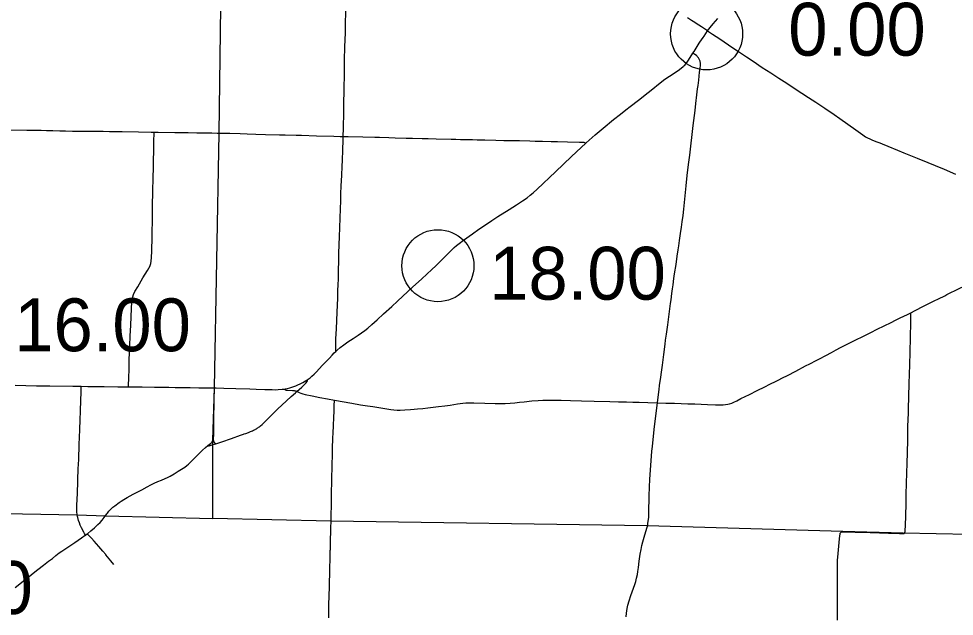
# Model space of a CAD drawing. Extents: x 1813937 to 1948437, y 826606 to 1022856.
# Drawn here: x 1890191 to 1909677, y 927491 to 939932 of the extents above; entities that cross this region are included whole.
import ezdxf

# ---------------------------------------------------------------- set-up
doc = ezdxf.new("R2010")
doc.units = 0
for name, color, linetype in [('Default', 7, 'Continuous'), ('GM_X_County_Road', 7, 'Continuous'), ('GM_X_State_Route', 7, 'Continuous'), ('GM_X_Township', 7, 'Continuous'), ('GM_X_Township_Road', 7, 'Continuous'), ('GM_X_US_Route', 7, 'Continuous')]:
    doc.layers.add(name, color=color, linetype=linetype)

msp = doc.modelspace()

# ---------------------------------------------------------------- linework, layer by layer
at = {"layer": 'Default'}
for centre in [(1904519, 939617), (1898922, 934790)]:
    msp.add_circle(centre, 750, dxfattribs=at)
at = {"layer": 'GM_X_County_Road'}
for points in [[(1904539, 939679), (1904643, 939612), (1904793, 939513), (1905065, 939329), (1905201, 939237), (1905351, 939138), (1905487, 939046), (1905678, 938919), (1905857, 938803), (1906022, 938695), (1906188, 938590), (1906366, 938473), (1906641, 938294), (1906791, 938194), (1906983, 938068), (1907172, 937938), (1907294, 937854), (1907629, 937617), (1907775, 937512), (1907830, 937476), (1907872, 937452), (1907916, 937430), (1907976, 937405), (1908067, 937369), (1908128, 937345), (1908173, 937326), (1908294, 937277), (1908492, 937196), (1908628, 937141), (1908734, 937097), (1908901, 937029), (1909129, 936936), (1909281, 936875), (1909463, 936801), (1909705, 936699)], [(1903493, 931936), (1903509, 932050), (1903530, 932212), (1903540, 932294), (1903564, 932472), (1903577, 932570), (1903597, 932716), (1903611, 932830), (1903625, 932944), (1903653, 933155), (1903664, 933237), (1903682, 933367), (1903708, 933562), (1903730, 933724), (1903767, 934001), (1903778, 934082), (1903795, 934212), (1903809, 934309), (1903821, 934390), (1903839, 934520), (1903852, 934618), (1903882, 934812), (1903907, 934991), (1903926, 935121), (1903938, 935202), (1903956, 935315), (1903975, 935462), (1903995, 935591), (1904012, 935705), (1904030, 935835), (1904045, 935965), (1904068, 936177), (1904095, 936455), (1904116, 936667), (1904142, 936895), (1904166, 937091), (1904242, 937710), (1904279, 938019), (1904296, 938166), (1904317, 938345), (1904332, 938475), (1904341, 938540), (1904355, 938654), (1904373, 938817), (1904383, 938898), (1904389, 938964), (1904390, 938997), (1904389, 939013), (1904387, 939030), (1904384, 939046), (1904379, 939062), (1904373, 939078), (1904366, 939092), (1904357, 939107), (1904347, 939120), (1904337, 939133), (1904325, 939145), (1904313, 939156), (1904288, 939177), (1904275, 939187), (1904233, 939213)], [(1889984, 937621), (1890362, 937614), (1890493, 937613), (1890657, 937609), (1890771, 937608), (1890902, 937604), (1891050, 937601), (1891165, 937597), (1891312, 937592), (1891542, 937590), (1891738, 937590), (1891820, 937590), (1891952, 937588), (1892083, 937586), (1892198, 937584), (1892345, 937582), (1892689, 937577), (1892951, 937573), (1893012, 937572)], [(1893012, 937572), (1893099, 937571), (1893443, 937565), (1893558, 937563), (1893722, 937560), (1893902, 937557), (1894034, 937555), (1894214, 937553), (1894322, 937551)], [(1894322, 937551), (1894378, 937550), (1894591, 937547), (1894804, 937542), (1894952, 937537), (1895132, 937531), (1895329, 937524), (1895624, 937517), (1895739, 937514), (1895968, 937509), (1896083, 937505), (1896394, 937497), (1896755, 937485), (1896886, 937481), (1896950, 937481)], [(1896950, 937481), (1897050, 937480), (1897362, 937471), (1897607, 937465), (1897706, 937463), (1897903, 937458), (1898034, 937455), (1898263, 937448), (1898394, 937445), (1898591, 937440), (1898722, 937438), (1898886, 937432), (1899198, 937423), (1899296, 937421), (1899394, 937419), (1899460, 937418), (1899640, 937414), (1899739, 937411), (1899903, 937408), (1900132, 937403), (1900296, 937400), (1900476, 937397), (1900623, 937394), (1900837, 937388), (1900951, 937385), (1901099, 937383), (1901279, 937379), (1901411, 937374), (1901624, 937371), (1901870, 937365), (1901919, 937364), (1901960, 937359), (1901991, 937350), (1902007, 937345)], [(1908770, 933811), (1908784, 933818), (1908847, 933850), (1909052, 933953), (1909258, 934056), (1909346, 934100), (1909478, 934165), (1909520, 934187), (1909561, 934208), (1909737, 934294), (1909928, 934388), (1910002, 934423), (1910066, 934451), (1910109, 934467), (1910139, 934476)], [(1903493, 931936), (1903669, 931930), (1903850, 931925), (1904129, 931917), (1904276, 931912), (1904539, 931903), (1904703, 931896), (1904801, 931894), (1904866, 931895), (1904915, 931899), (1904963, 931906), (1904995, 931914), (1905041, 931930), (1905086, 931949), (1905145, 931977), (1905233, 932022), (1905409, 932109), (1905571, 932189), (1905733, 932269), (1905836, 932320), (1905967, 932387), (1906011, 932410), (1906098, 932455), (1906200, 932507), (1906376, 932596), (1906580, 932702), (1906667, 932747), (1906798, 932815), (1906871, 932853), (1907001, 932922), (1907117, 932983), (1907219, 933037), (1907305, 933084), (1907349, 933107), (1907407, 933137), (1907554, 933210), (1907642, 933253), (1907760, 933311), (1907937, 933398), (1908072, 933466), (1908216, 933536), (1908362, 933610), (1908450, 933654), (1908494, 933676), (1908553, 933705), (1908700, 933777), (1908770, 933811)], [(1894243, 931170), (1894245, 931178), (1894248, 931195), (1894250, 931210), (1894253, 931242), (1894255, 931291), (1894254, 931438), (1894254, 931521), (1894255, 931636), (1894257, 931718), (1894259, 931833), (1894265, 932062), (1894268, 932177), (1894268, 932210), (1894269, 932245)], [(1895713, 932221), (1895735, 932210), (1895746, 932204), (1895758, 932200), (1895768, 932198), (1895780, 932196), (1895895, 932192), (1895928, 932190), (1895944, 932187), (1895960, 932182), (1895976, 932177), (1895986, 932172)], [(1895986, 932172), (1896006, 932162), (1896035, 932147), (1896064, 932134), (1896110, 932119), (1896157, 932108), (1896301, 932079), (1896462, 932047), (1896622, 932016), (1896769, 931987)], [(1896769, 931987), (1897132, 931926), (1897310, 931896), (1897455, 931873), (1897569, 931857), (1897860, 931808), (1897941, 931796), (1898006, 931788), (1898072, 931784), (1898137, 931784), (1898235, 931787), (1898350, 931795), (1898431, 931802), (1898497, 931808), (1898611, 931820), (1898709, 931830), (1898937, 931855), (1899067, 931871), (1899181, 931888), (1899327, 931913), (1899441, 931928), (1899506, 931934), (1899572, 931936), (1899671, 931935), (1899900, 931929), (1900113, 931924), (1900211, 931922), (1900326, 931923), (1900424, 931928), (1900522, 931936), (1900620, 931947), (1900717, 931959), (1900881, 931975), (1901012, 931986), (1901110, 931991), (1901159, 931992), (1901324, 931991), (1901488, 931988), (1901685, 931983), (1901914, 931978), (1902177, 931971), (1902505, 931962), (1902685, 931958), (1902849, 931954), (1902980, 931951), (1903112, 931947), (1903292, 931941), (1903489, 931934), (1903493, 931936)], [(1903292, 929398), (1903297, 929419), (1903304, 929468), (1903312, 929549), (1903315, 929615), (1903317, 929746), (1903319, 929894), (1903323, 929992), (1903330, 930189), (1903338, 930336), (1903381, 930925), (1903390, 931023), (1903429, 931382), (1903475, 931773), (1903493, 931936)], [(1892040, 929638), (1892069, 929677), (1892091, 929702), (1892126, 929737), (1892151, 929759), (1892190, 929789), (1892282, 929858), (1892322, 929887), (1892378, 929922), (1892449, 929964), (1892578, 930035), (1892753, 930126), (1892869, 930188), (1892942, 930226), (1893016, 930261), (1893091, 930294), (1893167, 930325), (1893242, 930356), (1893287, 930378), (1893344, 930408), (1893429, 930458), (1893513, 930509), (1893583, 930552), (1893651, 930598), (1893690, 930627), (1893728, 930658), (1893765, 930691), (1893834, 930760), (1893948, 930878), (1894019, 930947), (1894080, 931003), (1894127, 931043)], [(1894127, 931043), (1894184, 931086), (1894197, 931097), (1894208, 931108), (1894213, 931115), (1894218, 931121), (1894223, 931127), (1894227, 931134), (1894231, 931141), (1894234, 931148), (1894238, 931156), (1894240, 931163), (1894243, 931170)], [(1891617, 929206), (1891630, 929216), (1891693, 929268), (1891767, 929333), (1891839, 929400), (1891885, 929446), (1891929, 929495), (1891971, 929545), (1892029, 929624), (1892040, 929638)], [(1902845, 927476), (1902850, 927558), (1902856, 927607), (1902865, 927655), (1902880, 927719), (1902907, 927813), (1902942, 927922), (1903023, 928155), (1903043, 928217), (1903059, 928281), (1903076, 928361), (1903087, 928426), (1903099, 928507), (1903116, 928637), (1903137, 928783), (1903153, 928880), (1903169, 928961), (1903188, 929040), (1903215, 929135), (1903274, 929323), (1903287, 929370), (1903292, 929398)], [(1890119, 928087), (1890285, 928222), (1890374, 928294), (1890527, 928417), (1890591, 928468), (1890710, 928557), (1890814, 928636), (1890892, 928697), (1890968, 928759), (1891033, 928809), (1891087, 928847), (1891360, 929030), (1891496, 929121), (1891578, 929177), (1891583, 929181)], [(1891583, 929181), (1891617, 929206)], [(1892007, 928776), (1891946, 928848), (1891858, 928944), (1891760, 929054), (1891705, 929114), (1891649, 929173), (1891617, 929206)], [(1892174, 928571), (1892113, 928647), (1892009, 928773), (1892007, 928776)]]:
    msp.add_lwpolyline(points, dxfattribs=at)
at = {"layer": 'GM_X_State_Route'}
msp.add_lwpolyline([(1904539, 939679), (1904411, 939764), (1904301, 939834), (1904275, 939851), (1904204, 939897), (1904123, 939952)], dxfattribs=at)
at = {"layer": 'GM_X_Township'}
for points in [[(1915561, 944982), (1915495, 939674), (1915415, 934338), (1915377, 931981), (1915316, 929031), (1912650, 929114), (1909986, 929194), (1908612, 929220), (1907353, 929253), (1903279, 929371), (1896692, 929473), (1894233, 929528), (1894236, 931068), (1894237, 931156), (1894267, 932250), (1894363, 937552), (1894401, 940177)], [(1888752, 929651), (1891412, 929604), (1892001, 929584), (1894233, 929528)]]:
    msp.add_lwpolyline(points, dxfattribs=at)
at = {"layer": 'GM_X_Township_Road'}
for points in [[(1896950, 937481), (1896954, 937656), (1896961, 937984), (1896965, 938197), (1896970, 938410), (1896973, 938542), (1896976, 938705), (1896979, 938951), (1896980, 939066), (1896987, 939345), (1896996, 939640), (1897001, 939804), (1897006, 940099)], [(1892927, 934791), (1892944, 934835), (1892953, 934882), (1892959, 934964), (1892963, 935095), (1892969, 935391), (1892974, 935522), (1892979, 935686), (1892980, 935800), (1892980, 936014), (1892987, 936359), (1892992, 936605), (1892998, 936851), (1893000, 936983), (1893003, 937180), (1893008, 937393), (1893011, 937541), (1893012, 937572)], [(1896795, 933003), (1896794, 933068), (1896794, 933117), (1896799, 933265), (1896807, 933478), (1896822, 933822), (1896829, 933969), (1896836, 934117), (1896841, 934264), (1896846, 934395), (1896849, 934510), (1896854, 934674), (1896857, 934903), (1896861, 935051), (1896871, 935395), (1896879, 935575), (1896888, 935788), (1896895, 935968), (1896899, 936149), (1896902, 936296), (1896907, 936444), (1896918, 936673), (1896927, 936853), (1896932, 936984), (1896941, 937197), (1896948, 937410), (1896950, 937481)], [(1892478, 932266), (1892480, 932307), (1892486, 932439), (1892491, 932652), (1892495, 932832), (1892508, 933128), (1892516, 933325), (1892526, 933554), (1892540, 933899), (1892547, 934030), (1892556, 934096), (1892567, 934144), (1892584, 934191), (1892613, 934250), (1892669, 934351), (1892779, 934534), (1892872, 934689), (1892926, 934790), (1892927, 934791)], [(1908656, 929285), (1908657, 929297), (1908660, 929360), (1908667, 929606), (1908673, 929819), (1908678, 930032), (1908690, 930475), (1908698, 930671), (1908699, 930737), (1908702, 930835), (1908706, 930966), (1908708, 931097), (1908712, 931277), (1908712, 931359), (1908713, 931441), (1908718, 931588), (1908722, 931719), (1908726, 931867), (1908729, 932014), (1908732, 932145), (1908735, 932260), (1908738, 932391), (1908741, 932473), (1908743, 932554), (1908749, 932702), (1908752, 932784), (1908756, 932931), (1908758, 932996), (1908760, 933095), (1908762, 933193), (1908765, 933307), (1908768, 933406), (1908771, 933504), (1908774, 933651), (1908775, 933750), (1908774, 933782), (1908772, 933798), (1908770, 933811)], [(1895986, 932172), (1896085, 932264), (1896134, 932309), (1896168, 932344), (1896197, 932376), (1896200, 932380), (1896202, 932384), (1896205, 932392), (1896207, 932399), (1896208, 932409), (1896211, 932422)], [(1891418, 930140), (1891421, 930214), (1891424, 930329), (1891433, 930558), (1891441, 930754), (1891452, 931065), (1891464, 931376), (1891473, 931589), (1891478, 931752), (1891485, 931998), (1891490, 932145), (1891493, 932243), (1891494, 932279)], [(1894294, 931083), (1894423, 931126), (1894625, 931195), (1894812, 931259), (1894874, 931281), (1894890, 931286), (1894921, 931297), (1894977, 931318), (1895019, 931335), (1895043, 931345), (1895060, 931353), (1895084, 931364), (1895101, 931372), (1895113, 931379), (1895126, 931386), (1895141, 931396), (1895156, 931404), (1895173, 931416), (1895189, 931427), (1895203, 931437), (1895213, 931444), (1895225, 931453), (1895262, 931485), (1895309, 931530), (1895378, 931601), (1895412, 931637), (1895517, 931742), (1895586, 931811), (1895671, 931889), (1895867, 932065), (1895953, 932141), (1895986, 932172)], [(1896700, 929539), (1896705, 929862), (1896708, 930043), (1896713, 930320), (1896715, 930435), (1896717, 930533), (1896722, 930696), (1896725, 930794), (1896729, 930974), (1896737, 931203), (1896741, 931301), (1896748, 931464), (1896755, 931627), (1896760, 931758), (1896765, 931872), (1896769, 931987)], [(1894127, 931043), (1894141, 931039), (1894148, 931038), (1894151, 931038), (1894155, 931038), (1894158, 931038), (1894161, 931039), (1894220, 931059), (1894241, 931066)], [(1894241, 931066), (1894294, 931083)], [(1894243, 931170), (1894248, 931147), (1894254, 931126), (1894257, 931119), (1894260, 931113), (1894264, 931107), (1894268, 931102), (1894275, 931097), (1894281, 931092), (1894294, 931083)], [(1891405, 929654), (1891403, 929675), (1891401, 929740), (1891402, 929806), (1891407, 929920), (1891415, 930051), (1891415, 930084), (1891416, 930100), (1891418, 930133), (1891418, 930140)], [(1891418, 929565), (1891412, 929594), (1891407, 929626), (1891405, 929654)], [(1891583, 929181), (1891564, 929216), (1891548, 929244), (1891502, 929331), (1891474, 929390), (1891455, 929436), (1891440, 929482), (1891422, 929546), (1891418, 929565)], [(1896682, 928879), (1896684, 928974), (1896688, 929074), (1896692, 929262), (1896700, 929539)], [(1907335, 929246), (1907355, 929248), (1907385, 929249), (1907467, 929246), (1907615, 929240), (1907926, 929232), (1908304, 929222), (1908533, 929213), (1908599, 929212), (1908615, 929214), (1908631, 929216), (1908641, 929223), (1908649, 929237), (1908654, 929255), (1908656, 929285)], [(1907242, 927413), (1907242, 927544), (1907242, 927659), (1907242, 927807), (1907243, 927889), (1907242, 928003), (1907242, 928167), (1907245, 928315), (1907242, 928413), (1907243, 928479), (1907244, 928577), (1907247, 928659), (1907253, 928724), (1907285, 929100), (1907291, 929165), (1907297, 929197), (1907303, 929218), (1907308, 929229), (1907314, 929237), (1907321, 929241), (1907335, 929246)], [(1896649, 927459), (1896650, 927519), (1896653, 927715), (1896659, 927928), (1896662, 928091), (1896665, 928239), (1896668, 928337), (1896672, 928484), (1896677, 928696), (1896681, 928860), (1896682, 928879)]]:
    msp.add_lwpolyline(points, dxfattribs=at)
at = {"layer": 'GM_X_US_Route'}
for points in [[(1903435, 938502), (1903484, 938541), (1903513, 938565), (1903587, 938622), (1903652, 938672), (1903747, 938737), (1903924, 938855), (1903990, 938903), (1904028, 938934), (1904043, 938948), (1904064, 938968), (1904086, 938992), (1904116, 939030), (1904144, 939070), (1904233, 939213), (1904257, 939251), (1904367, 939421), (1904381, 939444), (1904445, 939543), (1904466, 939571), (1904539, 939679), (1904593, 939750), (1904656, 939827), (1904753, 939938)], [(1890119, 932300), (1890562, 932291), (1890661, 932289), (1890841, 932289), (1891317, 932281), (1891494, 932279), (1891629, 932278), (1891974, 932274), (1892253, 932270), (1892449, 932266), (1892478, 932266), (1892581, 932265), (1892761, 932265), (1893023, 932261), (1893187, 932261), (1893318, 932258), (1893450, 932257), (1893581, 932255), (1893761, 932251), (1893942, 932249), (1894139, 932247), (1894269, 932245), (1894303, 932245), (1894466, 932241), (1894713, 932233), (1895008, 932223), (1895139, 932219), (1895319, 932213), (1895467, 932210), (1895532, 932208), (1895598, 932210), (1895679, 932216), (1895713, 932221), (1895744, 932225), (1895792, 932234), (1895839, 932247), (1895902, 932267), (1895963, 932289), (1896008, 932308), (1896053, 932329), (1896110, 932360), (1896166, 932393), (1896211, 932422), (1896221, 932429), (1896261, 932458), (1896298, 932489), (1896347, 932533), (1896392, 932580), (1896515, 932713), (1896661, 932868), (1896717, 932928), (1896764, 932975), (1896795, 933003), (1896824, 933030), (1896887, 933084), (1896965, 933144), (1897045, 933202), (1897154, 933275), (1897264, 933346), (1897332, 933392), (1897398, 933440), (1897461, 933492), (1897548, 933567), (1897658, 933666), (1897791, 933787), (1897960, 933943), (1898081, 934054), (1898189, 934155), (1898395, 934342), (1898589, 934519), (1898795, 934708), (1898878, 934787), (1899052, 934961), (1899190, 935101), (1899261, 935170), (1899310, 935213), (1899362, 935254), (1899455, 935322), (1899643, 935454), (1899777, 935548), (1899952, 935670), (1900048, 935734), (1900172, 935814), (1900409, 935961), (1900561, 936058), (1900684, 936139), (1900778, 936205), (1900843, 936255), (1900906, 936307), (1900991, 936384), (1901373, 936745), (1901706, 937062), (1901908, 937254), (1902005, 937343), (1902007, 937345), (1902201, 937517), (1902364, 937656), (1902580, 937832), (1902723, 937943), (1902839, 938034), (1902928, 938107), (1903097, 938236), (1903304, 938397), (1903435, 938502)]]:
    msp.add_lwpolyline(points, dxfattribs=at)

# ---------------------------------------------------------------- texts
at = {"layer": 'Default'}
for s, p in [('0.00', (1906219, 939163)), ('18.00', (1899989, 934083)), ('16.00', (1890097, 933009)), ('10.00', (1886805, 927538))]:
    msp.add_text(s, height=1100, dxfattribs=at).set_placement(p)

doc.saveas('drawing.dxf')
